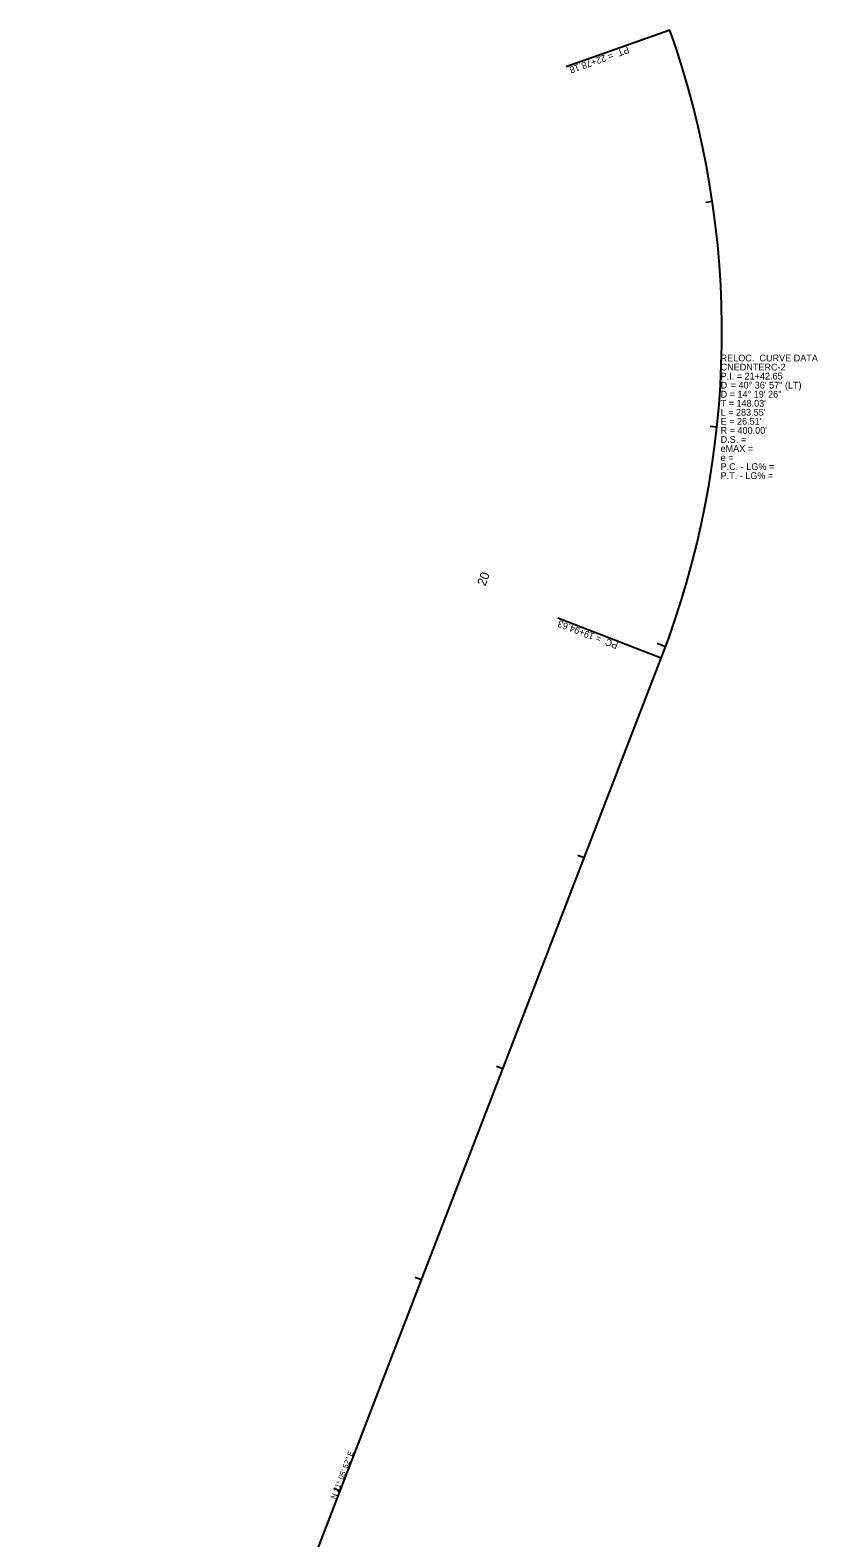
# Model space of a CAD drawing. Extents: x 2004693 to 2005101, y 1136556 to 1137889.
# Drawn here: x 2004753 to 2005101, y 1137223 to 1137889 of the extents above; entities that cross this region are included whole.
import ezdxf

# ---------------------------------------------------------------- set-up
doc = ezdxf.new("R2010")
doc.units = 0
for name, color, linetype in [('RD_HC_CL_Rel', 7, 'Continuous'), ('RD_HC_Data_Rel', 7, 'Continuous'), ('RD_HC_Data_Tic_Rel', 7, 'Continuous'), ('RD_HC_TX_Rel_Sta20', 7, 'Continuous')]:
    doc.layers.add(name, color=color, linetype=linetype)

msp = doc.modelspace()

# ---------------------------------------------------------------- linework, layer by layer
at = {"layer": 'RD_HC_CL_Rel'}
msp.add_line((2004752.64, 1136888.36), (2005031.77, 1137611.81), dxfattribs=at)
msp.add_arc((2004658.58, 1137755.79), 400, 338.90217, 19.51796, dxfattribs=at)
at = {"layer": 'RD_HC_Data_Rel'}
for p, q in [((2005035.59, 1137889.44), (2004989.73, 1137873.18)), ((2005031.77, 1137611.81), (2004986.02, 1137629.46))]:
    msp.add_line(p, q, dxfattribs=at)
at = {"layer": 'RD_HC_Data_Tic_Rel'}
for p, q in [((2005054.37, 1137813.67), (2005051.4, 1137813.24)), ((2005056.39, 1137713.95), (2005053.4, 1137714.27)), ((2005033.67, 1137616.84), (2005029.92, 1137618.23)), ((2004997.7, 1137523.53), (2004994.91, 1137524.61)), ((2004961.71, 1137430.23), (2004958.91, 1137431.31)), ((2004925.71, 1137336.93), (2004922.91, 1137338.01)), ((2004889.72, 1137243.64), (2004886.92, 1137244.72))]:
    msp.add_line(p, q, dxfattribs=at)

# ---------------------------------------------------------------- texts
at = {"layer": 'RD_HC_Data_Rel'}
for s, height, rotation, p in [('PT  = 22+78.18', 3, 199.51796, (2005016.91, 1137882.28)), ('PC  = 19+94.63', 3, 158.90217, (2005012.93, 1137618.54)), ('N 21%%d 05\' 52" E', 2.4, 68.90217, (2004887.71, 1137239.83))]:
    msp.add_text(s, height=height, rotation=rotation, dxfattribs=at).set_placement(p)
for s, p in [('CNEDNTERC-2', (2005058, 1137739)), ('RELOC.  CURVE DATA', (2005058, 1137743)), ('P.I. = 21+42.65', (2005058, 1137735)), ('D', (2005058, 1137731)), ('    = 40%%d 36\' 57" (LT)', (2005058, 1137731)), ('D = 14%%d 19\' 26"', (2005058, 1137727)), ("T = 148.03'", (2005058, 1137723)), ("L = 283.55'", (2005058, 1137719)), ("E = 26.51'", (2005058, 1137715)), ("R = 400.00'", (2005058, 1137711)), ('D.S. = ', (2005058, 1137707)), ('eMAX = ', (2005058, 1137703)), ('e = ', (2005058, 1137699)), ('P.C. - LG% =', (2005058, 1137695)), ('P.T. - LG% =', (2005058, 1137691))]:
    msp.add_text(s, height=3, dxfattribs=at).set_placement(p)
at = {"layer": 'RD_HC_TX_Rel_Sta20'}
msp.add_text('20', height=4, rotation=69.67189, dxfattribs=at).set_placement((2004953.92, 1137643.38))

doc.saveas('drawing.dxf')
